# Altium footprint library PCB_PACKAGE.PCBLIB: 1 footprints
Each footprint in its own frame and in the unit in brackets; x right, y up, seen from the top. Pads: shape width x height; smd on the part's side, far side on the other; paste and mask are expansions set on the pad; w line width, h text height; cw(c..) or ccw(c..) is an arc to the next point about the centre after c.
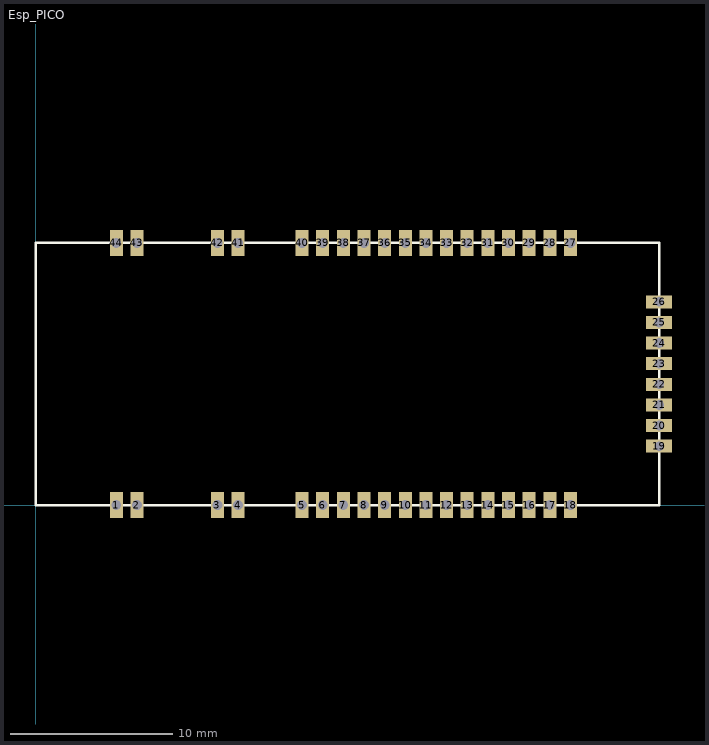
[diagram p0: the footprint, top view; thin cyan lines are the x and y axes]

## Esp_PICO [mm]
pads (44):
  rect 0.8x1.6 hole 0.6: 1(4.953,0) 2(6.223,0) 3(11.176,0) 4(12.446,0) 5(16.383,0) 6(17.653,0) 7(18.923,0) 8(20.193,0) 9(21.463,0) 10(22.733,0) 11(24.003,0) 12(25.273,0) 13(26.543,0) 14(27.813,0) 15(29.083,0) 16(30.353,0) 17(31.623,0) 18(32.893,0) 27(32.893,16.129) 28(31.623,16.129) 29(30.353,16.129) 30(29.083,16.129) 31(27.813,16.129) 32(26.543,16.129) 33(25.273,16.129) 34(24.003,16.129) 35(22.733,16.129) 36(21.463,16.129) 37(20.193,16.129) 38(18.923,16.129) 39(17.653,16.129) 40(16.383,16.129) 41(12.446,16.129) 42(11.176,16.129) 43(6.223,16.129) 44(4.953,16.129)
  rect 1.6x0.8 hole 0.6: 19(38.354,3.619) 20(38.354,4.889) 21(38.354,6.159) 22(38.354,7.429) 23(38.354,8.7) 24(38.354,9.97) 25(38.354,11.239) 26(38.354,12.509)
Top Overlay:
  lines w0.152: 0,0 38.354,0 38.354,16.129 0,16.129 0,0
